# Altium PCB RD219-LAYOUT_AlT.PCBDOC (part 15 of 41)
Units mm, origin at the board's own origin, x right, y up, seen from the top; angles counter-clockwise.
Board outline 209.75 x 159.97 mm, 2 copper layers (TOP, BOTTOM), stack 0 mm thick; 398 components, 199 nets, 1469 pads, 0 vias.
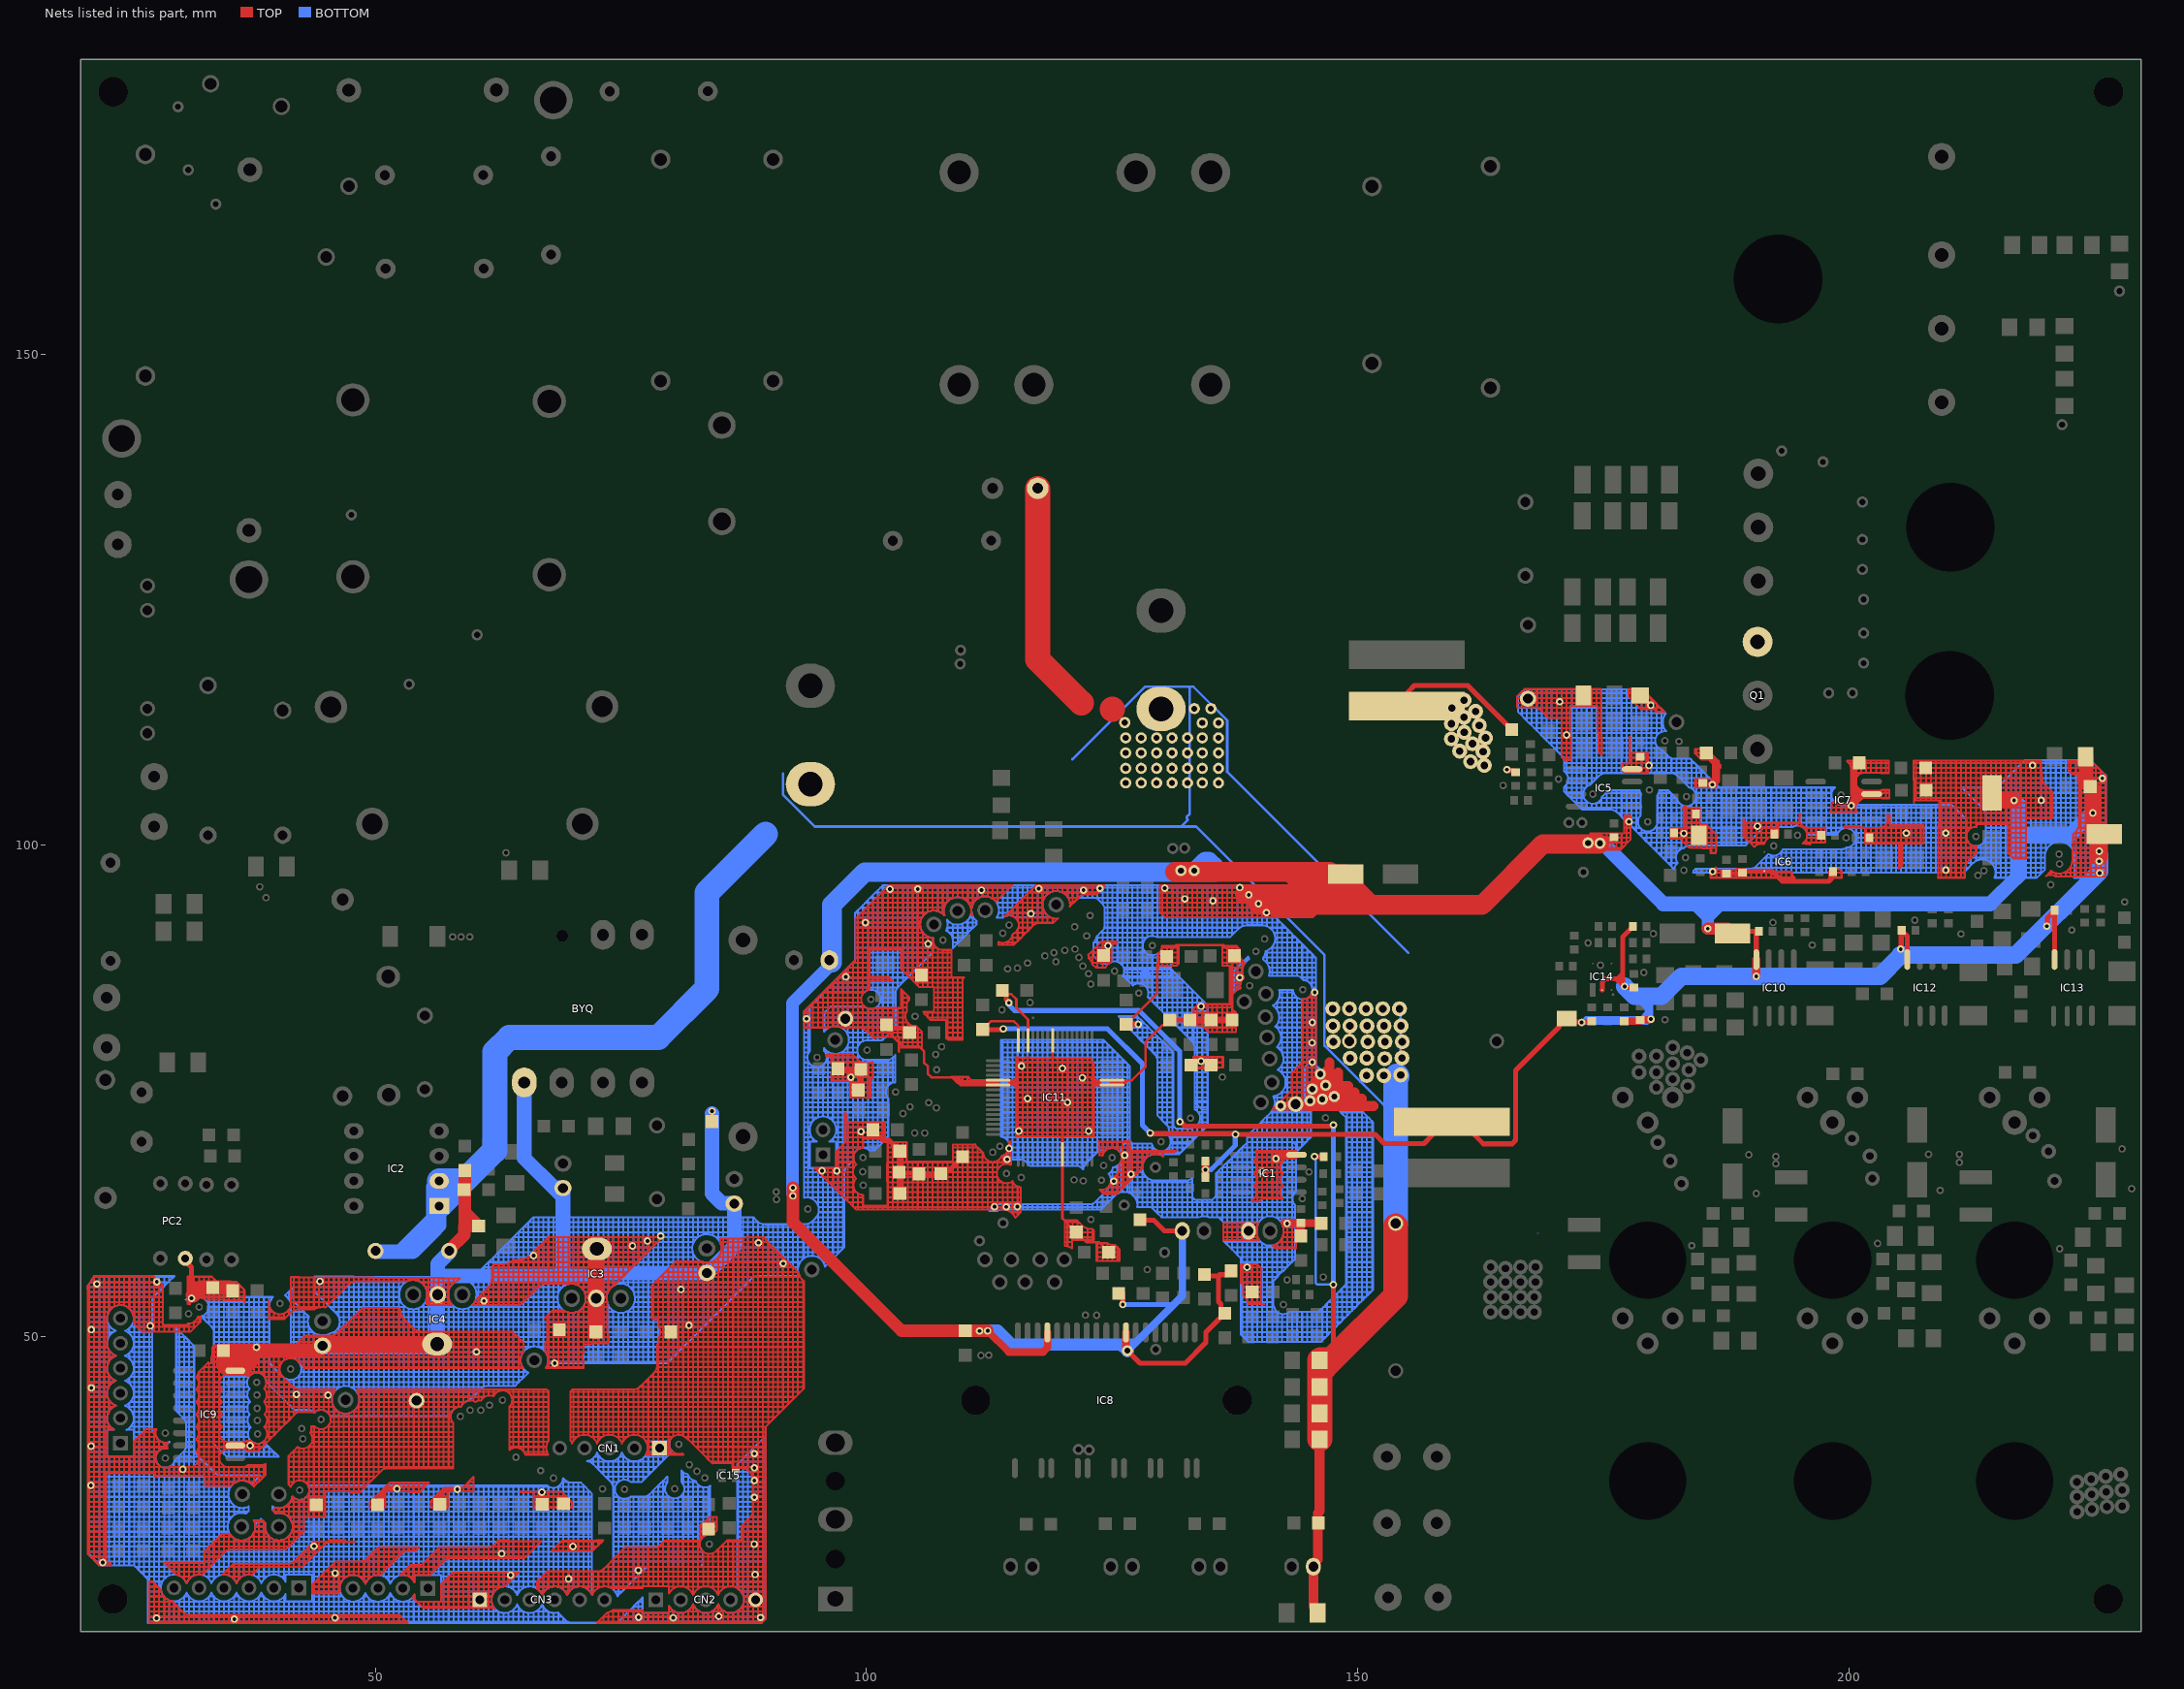
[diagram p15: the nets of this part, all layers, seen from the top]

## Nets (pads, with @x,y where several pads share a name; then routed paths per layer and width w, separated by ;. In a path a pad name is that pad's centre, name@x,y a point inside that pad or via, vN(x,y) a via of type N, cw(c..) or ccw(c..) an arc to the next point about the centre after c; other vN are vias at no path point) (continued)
GND: (continued)
  TOP w0.203: 127.569,66.736 127.569,67.244 ; 127.569,67.244 127.569,67.752 ; 127.569,67.244 128.058,67.244 ; 127.569,67.752 127.569,68.26 ; 127.569,67.752 128.077,67.752 ; 127.569,68.26 127.569,68.768 ; 127.569,68.26 128.077,68.26 ; 127.569,68.768 127.569,68.895 ; 127.569,68.768 128.077,68.768 ; 127.569,68.895 128.077,68.895 ; 127.658,66.736 128.058,67.136 128.058,67.234 cw(c129.41,67.234) 128.058,67.244 ; 128.058,67.244 cw(c129.41,67.234) 128.077,67.459 ; 128.077,67.459 cw(c129.41,67.234) 128.079,67.469 cw(c129.41,67.234) 128.161,67.752 ; 128.077,67.459 128.077,67.752 ; 128.077,67.752 128.077,68.26 ; 128.077,67.752 128.161,67.752 ; 128.077,68.26 128.077,68.768 ; 128.077,68.26 128.53,68.26 ; 128.077,68.768 128.585,68.768 ; 128.077,68.768 128.077,68.895 ; 128.077,68.895 128.585,68.895 ; 128.161,67.752 cw(c129.41,67.234) 128.53,68.26 ; 128.53,68.26 cw(c129.41,67.234) 128.585,68.305 ; 128.585,68.305 128.585,68.768 ; 128.585,68.768 128.585,68.895 ; 128.585,68.768 129.093,68.768 ; 128.585,68.895 129.093,68.895 ; 129.093,68.768 129.601,68.768 ; 129.093,68.768 129.093,68.895 ; 129.093,68.895 129.601,68.895 ; 129.601,68.572 cw(c129.41,67.234) 130.109,68.391 ; 129.601,68.572 129.601,68.768 ; 129.601,68.768 129.601,68.895 ; 129.601,68.768 130.109,68.768 ; 129.601,68.895 129.744,68.895 ccw(c129.983,69.848) 130.109,68.874 ; 129.682,87.738 130.109,87.738 ; 129.682,87.738 129.682,88.026 129.682,88.072 ; 129.682,88.072 129.728,88.072 C45.2@130.109,88.072 ; 129.682,88.072 129.682,88.58 ; 129.682,88.58 C45.2@130.109,88.58 ; 129.682,88.58 129.682,89.014 ccw(c129.091,89.799) 129.769,89.088 ; 129.769,89.088 ccw(c129.091,89.799) 129.876,89.208 ccw(c129.091,89.799) 130.052,89.596 ; 129.769,89.088 C45.2@130.109,89.088 ; 129.837,93.66 129.837,94.168 ; 129.837,93.66 129.837,93.217 129.902,93.152 ; 129.837,93.66 130.109,93.66 ; 129.837,94.168 129.837,94.676 ; 129.837,94.168 130.109,94.168 ; 129.837,94.676 129.837,95.184 ; 129.837,94.676 130.109,94.676 ; 129.837,95.184 129.837,95.692 ; 129.837,95.184 130.109,95.184 ; 129.837,95.692 129.837,95.946 130.109,95.946 ; 129.837,95.692 pad.@130.109,95.692 ; 129.902,93.152 130.109,92.945 ; 129.902,93.152 130.109,93.152 ; 130.052,89.596 ccw(c129.091,89.799) 130.073,89.756 ; 130.052,89.596 130.109,89.596 ; 130.073,89.756 130.109,89.756 ; 130.109,68.391 cw(c129.41,67.234) 130.2,68.33 ; 130.109,68.391 130.109,68.768 ; 130.109,68.768 130.617,68.768 ; 130.109,68.768 130.109,68.874 ; 130.109,68.874 ccw(c129.983,69.848) 130.22,68.895 130.617,68.895 ; 130.109,87.738 130.617,87.738 ; 130.109,87.738 C45.2@130.109,88.072 ; C45.2@130.109,88.072 130.109,88.453 C45.2@130.109,88.58 ; C45.2@130.109,88.072 C45.2@130.617,88.072 ; C45.2@130.109,88.58 130.236,88.58 C45.2@130.617,88.58 ; C45.2@130.109,88.58 C45.2@130.109,89.088 ; C45.2@130.109,89.088 130.109,89.596 ; C45.2@130.109,89.088 C45.2@130.617,89.088 ; 130.109,89.596 130.617,89.596 ; 130.109,89.596 130.109,89.756 ; 130.109,89.756 130.617,89.756 ; 130.109,92.945 130.109,93.152 ; 130.109,92.945 130.351,92.703 130.617,92.703 ; 130.109,93.152 130.109,93.66 ; 130.109,93.152 130.617,93.152 ; 130.109,93.66 130.109,94.168 ; 130.109,93.66 130.617,93.66 ; 130.109,94.168 130.109,94.676 ; 130.109,94.168 130.617,94.168 ; 130.109,94.676 130.109,95.184 ; 130.109,94.676 130.617,94.676 ; 130.109,95.184 130.617,95.184 ; 130.109,95.184 pad.@130.109,95.692 ; pad.@130.109,95.692 130.109,95.946 ; pad.@130.109,95.692 pad.@130.617,95.692 ; 130.109,95.946 130.617,95.946 ; 130.2,68.33 130.2,68.754 130.617,68.754 ; 130.617,68.754 131.125,68.754 ; 130.617,68.754 130.617,68.768 ; 130.617,68.768 131.125,68.768 ; 130.617,68.768 130.617,68.895 ; 130.617,68.895 131.125,68.895 ; 130.617,87.738 C45.2@130.617,88.072 ; 130.617,87.738 131.125,87.738 ; C45.2@130.617,88.072 C45.2@130.617,88.58 ; C45.2@130.617,88.072 C45.2@131.125,88.072 ; C45.2@130.617,88.58 C45.2@131.125,88.58 ; C45.2@130.617,88.58 130.617,88.961 C45.2@130.617,89.088 ; C45.2@130.617,89.088 130.744,89.088 C45.2@131.125,89.088 ; C45.2@130.617,89.088 130.617,89.596 ; 130.617,89.596 130.617,89.756 ; 130.617,89.596 131.125,89.596 ; 130.617,89.756 131.125,89.756 ; 130.617,92.703 130.617,93.152 ; 130.617,92.703 131.125,92.703 ; 130.617,93.152 130.617,93.66 ; 130.617,93.152 131.125,93.152 ; 130.617,93.66 130.617,94.168 ; 130.617,93.66 131.125,93.66 ; 130.617,94.168 130.617,94.676 ; 130.617,94.168 131.125,94.168 ; 130.617,94.676 130.617,95.184 ; 130.617,94.676 131.125,94.676 ; 130.617,95.184 131.125,95.184 ; 130.617,95.184 pad.@130.617,95.692 ; pad.@130.617,95.692 130.617,95.946 ; pad.@130.617,95.692 131.125,95.692 ; 130.617,95.946 131.125,95.946 ; 131.125,68.754 131.125,68.768 ; 131.125,68.754 131.281,68.754 ; 131.125,68.768 131.125,68.895 ; 131.125,68.768 131.3,68.768 ; 131.125,87.738 C45.2@131.125,88.072 ; 131.125,87.738 131.555,87.738 131.633,87.815 ; C45.2@131.125,88.072 131.633,88.072 ; C45.2@131.125,88.072 C45.2@131.125,88.58 ; C45.2@131.125,88.58 131.633,88.58 ; C45.2@131.125,88.58 C45.2@131.125,89.088 ; C45.2@131.125,89.088 131.633,89.088 ; C45.2@131.125,89.088 131.125,89.469 131.125,89.596 ; 131.125,89.596 131.252,89.596 131.633,89.596 ; 131.125,89.596 131.125,89.756 ; 131.125,89.756 131.412,89.756 131.633,89.756 ; 131.125,92.703 131.125,93.152 ; 131.125,92.703 131.633,92.703 ; 131.125,93.152 131.125,93.66 ; 131.125,93.152 131.633,93.152 ; 131.125,93.66 131.125,94.168 ; 131.125,93.66 131.633,93.66 ; 131.125,94.168 131.125,94.676 ; 131.125,94.168 131.633,94.168 ; 131.125,94.676 131.125,95.184 ; 131.125,94.676 131.633,94.676 ; 131.125,95.184 131.125,95.692 ; 131.125,95.184 131.633,95.184 ; 131.125,95.692 131.125,95.946 ; 131.125,95.692 131.633,95.692 ; 131.125,95.946 131.633,95.946 ; 131.281,68.754 cw(c131.729,68.179) 131.3,68.768 ; 131.281,68.754 cw(c131.729,68.179) 131.3,68.768 ; 131.3,68.768 cw(c131.729,68.179) 131.59,68.894 ccw(c131.729,68.179) 131.3,68.768 ; 131.633,87.815 131.633,88.072 ; 131.633,87.815 131.778,87.961 131.778,88.072 ; 131.633,88.072 131.633,88.58 ; 131.633,88.072 131.778,88.072 ; 131.633,88.58 131.633,89.088 ; 131.633,88.58 131.778,88.58 ; 131.633,89.088 131.778,89.088 ; 131.633,89.088 131.633,89.596 ; 131.633,89.596 131.778,89.596 ; 131.633,89.596 131.633,89.756 ; 131.633,89.756 131.778,89.756 131.778,89.596 ; 131.633,92.703 131.633,93.152 ; 131.633,92.703 132.141,92.703 ; 131.633,93.152 131.633,93.66 ; 131.633,93.152 132.141,93.152 ; 131.633,93.66 131.633,94.168 ; 131.633,93.66 132.141,93.66 ; 131.633,94.168 131.633,94.676 ; 131.633,94.168 132.141,94.168 ; 131.633,94.676 131.633,95.184 ; 131.633,94.676 pad.@132.141,94.676 ; 131.633,95.184 131.633,95.692 ; 131.633,95.184 132.141,95.184 ; 131.633,95.692 131.633,95.946 ; 131.633,95.692 132.141,95.692 ; 131.633,95.946 132.141,95.946 ; 131.778,88.072 131.778,88.58 ; 131.778,88.58 131.778,89.088 ; 131.778,89.088 131.778,89.596 ; 132.141,92.703 132.141,93.152 ; 132.141,92.703 132.649,92.703 ; 132.141,93.152 132.141,93.66 ; 132.141,93.152 132.649,93.152 ; 132.141,93.66 132.141,94.168 ; 132.141,93.66 132.649,93.66 ; 132.141,94.168 132.649,94.168 ; 132.141,94.168 pad.@132.141,94.676 ; pad.@132.141,94.676 132.141,95.184 ; pad.@132.141,94.676 pad.@132.649,94.676 ; 132.141,95.184 132.141,95.692 ; 132.141,95.184 132.649,95.184 ; 132.141,95.692 132.141,95.946 ; 132.141,95.692 132.649,95.692 ; 132.141,95.946 132.649,95.946 ; 132.649,92.703 132.649,93.152 ; 132.649,92.703 133.157,92.703 ; 132.649,93.152 132.649,93.66 ; 132.649,93.152 133.157,93.152 ; 132.649,93.66 132.649,94.168 ; 132.649,93.66 133.157,93.66 ; 132.649,94.168 133.157,94.168 ; 132.649,94.168 pad.@132.649,94.676 ; pad.@132.649,94.676 132.649,95.184 ; pad.@132.649,94.676 133.157,94.676 ; 132.649,95.184 132.649,95.692 ; 132.649,95.184 133.157,95.184 ; 132.649,95.692 132.649,95.946 ; 132.649,95.692 133.157,95.692 ; 132.649,95.946 133.157,95.946 ; 133.157,92.703 133.157,93.152 ; 133.157,92.703 133.665,92.703 ; 133.157,93.152 133.157,93.66 ; 133.157,93.152 133.665,93.152 ; 133.157,93.66 133.157,94.168 ; 133.157,93.66 133.665,93.66 ; 133.157,94.168 133.157,94.676 ; 133.157,94.168 133.665,94.168 ; 133.157,94.676 133.157,95.184 ; 133.157,94.676 133.665,94.676 ; 133.157,95.184 133.157,95.692 ; 133.157,95.184 133.665,95.184 ; 133.157,95.692 133.157,95.946 ; 133.157,95.692 133.665,95.692 ; 133.157,95.946 133.665,95.946 ; C65.2@133.284,77.404 C65.2@133.665,77.404 ; C65.2@133.284,77.404 133.284,77.283 C65.2@133.665,77.283 ; C65.2@133.284,77.404 C65.2@133.284,77.912 ; C65.2@133.284,77.912 C65.2@133.665,77.912 ; C65.2@133.284,77.912 133.284,78.42 ; 133.284,78.42 133.665,78.42 ; 133.284,78.42 133.284,78.489 133.665,78.489 ; C43.1@133.284,81.976 133.665,81.976 ; C43.1@133.284,81.976 133.284,81.689 133.665,81.689 ; C43.1@133.284,81.976 133.284,82.23 C43.1@133.284,82.484 ; C43.1@133.284,82.484 133.665,82.484 ; C43.1@133.284,82.484 133.284,82.992 ; 133.284,82.992 133.665,82.992 ; 133.284,82.992 133.284,83.359 133.425,83.5 ; 133.425,83.5 133.665,83.5 ; 133.425,83.5 133.665,83.74 ; C65.2@133.665,77.283 134.173,77.283 ; C65.2@133.665,77.283 C65.2@133.665,77.404 ; C65.2@133.665,77.404 134.173,77.404 ; C65.2@133.665,77.404 C65.2@133.665,77.912 ; C65.2@133.665,77.912 pad.@134.173,77.912 ; C65.2@133.665,77.912 133.665,78.42 ; 133.665,78.42 133.665,78.489 ; 133.665,78.42 134.173,78.42 ; 133.665,78.489 134.173,78.489 ; 133.665,81.689 133.665,81.976 ; 133.665,81.689 133.843,81.689 ; 133.665,81.976 134.173,81.976 ; 133.665,81.976 133.665,82.23 133.665,82.484 ; 133.665,82.484 134.173,82.484 ; 133.665,82.484 133.665,82.992 ; 133.665,82.992 134.173,82.992 ; 133.665,82.992 133.665,83.5 ; 133.665,83.5 pad.@134.173,83.5 ; 133.665,83.5 133.665,83.74 ; 133.665,83.74 133.76,83.834 pad.@134.173,83.834 ; 133.665,92.703 133.665,93.152 ; 133.665,92.703 134.173,92.703 ; 133.665,93.152 133.665,93.66 ; 133.665,93.152 134.173,93.152 ; 133.665,93.66 133.665,94.168 ; 133.665,93.66 134.173,93.66 ; 133.665,94.168 133.665,94.676 ; 133.665,94.168 134.173,94.168 ; 133.665,94.676 133.665,95.184 ; 133.665,94.676 134.173,94.676 ; 133.665,95.184 133.665,95.692 ; 133.665,95.184 134.173,95.184 ; 133.665,95.692 133.665,95.946 ; 133.665,95.692 134.173,95.692 ; 133.665,95.946 134.173,95.946 ; 133.843,81.689 cw(c133.843,80.96) 134.173,81.609 ; 133.843,81.689 cw(c133.843,80.96) 134.173,81.609 ; 134.173,77.283 C56.2@134.681,77.283 ; 134.173,77.283 134.173,77.404 ; 134.173,77.404 C56.2@134.681,77.404 ; 134.173,77.404 pad.@134.173,77.912 ; pad.@134.173,77.912 C56.2@134.681,77.912 ; pad.@134.173,77.912 134.173,78.42 ; 134.173,78.42 134.681,78.42 ; 134.173,78.42 134.173,78.489 ; 134.173,78.489 134.681,78.489 ; 134.173,81.609 cw(c133.843,80.96) 134.358,81.475 ; 134.173,81.609 cw(c133.843,80.96) 134.358,81.475 ; 134.173,81.609 134.173,81.976 ; 134.173,81.976 C40.1@134.681,81.976 ; 134.173,81.976 134.173,82.23 134.173,82.484 ; 134.173,82.484 C40.1@134.681,82.484 ; 134.173,82.484 134.173,82.992 ; 134.173,82.992 134.681,82.992 ; 134.173,82.992 pad.@134.173,83.5 ; pad.@134.173,83.5 134.681,83.5 ; pad.@134.173,83.5 pad.@134.173,83.834 ; pad.@134.173,83.834 134.681,83.834 ; 134.173,92.703 134.173,93.152 ; 134.173,92.703 134.681,92.703 ; 134.173,93.152 134.173,93.66 ; 134.173,93.152 134.681,93.152 ; 134.173,93.66 134.173,94.168 ; 134.173,93.66 134.681,93.66 ; 134.173,94.168 134.173,94.676 ; 134.173,94.168 134.681,94.168 ; 134.173,94.676 134.173,95.184 ; 134.173,94.676 134.681,94.676 ; 134.173,95.184 134.173,95.692 ; 134.173,95.184 134.681,95.184 ; 134.173,95.692 134.173,95.946 ; 134.173,95.692 134.681,95.692 ; 134.173,95.946 134.681,95.946 ; 134.358,81.475 134.681,81.152 ; C56.2@134.681,77.283 C56.2@134.681,77.404 ; C56.2@134.681,77.283 C56.2@135.189,77.283 ; C56.2@134.681,77.404 C56.2@135.189,77.404 ; C56.2@134.681,77.404 C56.2@134.681,77.912 ; C56.2@134.681,77.912 134.681,78.42 ; C56.2@134.681,77.912 C56.2@135.189,77.912 ; 134.681,78.42 135.189,78.42 ; 134.681,78.42 134.681,78.489 ; 134.681,78.489 135.189,78.489 ; 134.681,81.152 134.841,80.992 135.189,80.992 ; 134.681,81.152 134.681,81.468 ; 134.681,81.468 135.189,81.468 ; 134.681,81.468 C40.1@134.681,81.976 ; C40.1@134.681,81.976 134.681,82.23 C40.1@134.681,82.484 ; C40.1@134.681,81.976 C40.1@135.189,81.976 ; C40.1@134.681,82.484 134.681,82.992 ; C40.1@134.681,82.484 C40.1@135.189,82.484 ; 134.681,82.992 135.189,82.992 ; 134.681,82.992 134.681,83.5 ; 134.681,83.5 135.189,83.5 ; 134.681,83.5 134.681,83.834 ; 134.681,83.834 135.189,83.834 ; 134.681,92.703 134.681,93.152 ; 134.681,92.703 135.189,92.703 ; 134.681,93.152 134.681,93.66 ; 134.681,93.152 135.189,93.152 ; 134.681,93.66 134.681,94.168 ; 134.681,93.66 135.189,93.66 ; 134.681,94.168 134.681,94.676 ; 134.681,94.168 pad.@135.189,94.168 ; 134.681,94.676 134.681,95.184 ; 134.681,94.676 pad.@135.189,94.676 ; 134.681,95.184 134.681,95.692 ; 134.681,95.184 135.189,95.184 ; 134.681,95.692 134.681,95.946 ; 134.681,95.692 135.189,95.692 ; 134.681,95.946 135.189,95.946 ; C56.2@135.189,77.283 C56.2@135.697,77.283 ; C56.2@135.189,77.283 C56.2@135.189,77.404 ; C56.2@135.189,77.404 C56.2@135.697,77.404 ; C56.2@135.189,77.404 C56.2@135.189,77.912 ; C56.2@135.189,77.912 C56.2@135.697,77.912 ; C56.2@135.189,77.912 135.189,78.42 ; 135.189,78.42 135.697,78.42 ; 135.189,78.42 135.189,78.489 ; 135.189,78.489 135.697,78.489 ; 135.189,80.992 135.189,81.468 ; 135.189,80.992 135.697,80.992 ; 135.189,81.468 C40.1@135.189,81.976 ; 135.189,81.468 135.697,81.468 ; C40.1@135.189,81.976 C40.1@135.697,81.976 ; C40.1@135.189,81.976 135.189,82.23 C40.1@135.189,82.484 ; C40.1@135.189,82.484 135.189,82.992 ; C40.1@135.189,82.484 C40.1@135.697,82.484 ; 135.189,82.992 135.189,83.5 ; 135.189,82.992 135.697,82.992 ; 135.189,83.5 135.189,83.834 ; 135.189,83.5 135.697,83.5 ; 135.189,83.834 135.697,83.834 ; 135.189,92.703 135.189,93.152 ; 135.189,92.703 135.697,92.703 ; 135.189,93.152 135.189,93.66 ; 135.189,93.152 135.697,93.152 ; 135.189,93.66 pad.@135.189,94.168 ; 135.189,93.66 135.697,93.66 ; pad.@135.189,94.168 pad.@135.189,94.676 ; pad.@135.189,94.168 135.697,94.168 ; pad.@135.189,94.676 135.189,95.184 ; pad.@135.189,94.676 135.697,94.676 ; 135.189,95.184 135.189,95.692 ; 135.189,95.184 135.697,95.184 ; 135.189,95.692 135.189,95.946 ; 135.189,95.692 135.697,95.692 ; 135.189,95.946 135.697,95.946 ; C56.2@135.697,77.283 C56.2@135.697,77.404 ; C56.2@135.697,77.404 136.109,77.404 ; C56.2@135.697,77.404 C56.2@135.697,77.912 ; C56.2@135.697,77.912 136.205,77.912 ; C56.2@135.697,77.912 135.697,78.42 ; 135.697,78.42 136.205,78.42 ; 135.697,78.42 135.697,78.489 ; 135.697,78.489 136.205,78.489 ; 135.697,80.992 135.697,81.468 ; 135.697,80.992 136.205,80.992 ; 135.697,81.468 136.205,81.468 ; 135.697,81.468 C40.1@135.697,81.976 ; C40.1@135.697,81.976 136.205,81.976 ; C40.1@135.697,81.976 135.697,82.23 C40.1@135.697,82.484 ; C40.1@135.697,82.484 136.205,82.484 ; C40.1@135.697,82.484 135.697,82.992 ; 135.697,82.992 136.205,82.992 ; 135.697,82.992 135.697,83.5 ; 135.697,83.5 136.205,83.5 ; 135.697,83.5 135.697,83.834 ; 135.697,83.834 136.205,83.834 ; 135.697,92.703 135.697,93.152 ; 135.697,92.703 136.205,92.703 ; 135.697,93.152 135.697,93.66 ; 135.697,93.152 136.205,93.152 ; 135.697,93.66 135.697,94.168 ; 135.697,93.66 136.205,93.66 ; 135.697,94.168 136.205,94.168 ; 135.697,94.168 135.697,94.676 ; 135.697,94.676 135.697,95.184 ; 135.697,94.676 136.205,94.676 ; 135.697,95.184 135.697,95.692 ; 135.697,95.184 136.205,95.184 ; 135.697,95.692 135.697,95.946 ; 135.697,95.692 136.205,95.692 ; 135.697,95.946 136.205,95.946 ; 136.109,77.404 cw(c136.214,76.427) 136.205,77.41 ; 136.205,77.41 cw(c136.214,76.427) 136.3,77.406 136.3,77.912 ; 136.205,77.41 136.205,77.912 ; 136.205,77.912 136.3,77.912 ; 136.205,77.912 136.205,78.42 ; 136.205,78.42 136.3,78.42 ; 136.205,78.42 136.205,78.489 ; 136.205,78.489 136.3,78.489 136.3,78.42 ; 136.205,80.992 136.205,81.468 ; 136.205,80.992 136.713,80.992 ; 136.205,81.468 136.205,81.976 ; 136.205,81.468 136.713,81.468 ; 136.205,81.976 136.205,82.23 136.205,82.484 ; 136.205,81.976 C41.1@136.713,81.976 ; 136.205,82.484 136.205,82.992 ; 136.205,82.484 C41.1@136.713,82.484 ; 136.205,82.992 136.205,83.5 ; 136.205,82.992 136.713,82.992 ; 136.205,83.5 136.713,83.5 ; 136.205,83.5 136.205,83.834 ; 136.205,83.834 136.713,83.834 ; 136.205,92.703 136.205,93.152 ; 136.205,92.703 136.713,92.703 ; 136.205,93.152 136.205,93.66 ; 136.205,93.152 136.713,93.152 ; 136.205,93.66 136.205,94.168 ; 136.205,93.66 136.713,93.66 ; 136.205,94.168 136.205,94.676 ; 136.205,94.168 136.713,94.168 ; 136.205,94.676 136.205,95.184 ; 136.205,94.676 136.713,94.676 ; 136.205,95.184 136.205,95.692 ; 136.205,95.184 136.713,95.184 ; 136.205,95.692 136.205,95.946 ; 136.205,95.692 136.713,95.692 ; 136.205,95.946 136.713,95.946 ; 136.212,88.072 136.212,88.58 ; 136.212,88.072 136.212,87.738 136.713,87.738 ; 136.212,88.072 136.713,88.072 ; 136.212,88.58 136.212,89.088 ; 136.212,88.58 136.713,88.58 ; 136.212,89.088 136.212,89.596 ; 136.212,89.088 136.713,89.088 ; 136.212,89.596 136.612,89.596 136.713,89.596 ; 136.212,89.596 136.212,89.756 136.452,89.756 136.713,89.756 ; 136.3,77.912 136.3,78.42 ; 136.332,60.132 136.332,60.64 ; 136.332,60.132 136.713,60.132 ; 136.332,60.132 136.332,59.825 136.713,59.825 ; 136.332,60.64 136.332,61.148 ; 136.332,60.64 136.713,60.64 ; 136.332,61.148 136.332,61.562 136.713,61.562 ; 136.332,61.148 136.713,61.148 ; 136.713,59.825 137.221,59.825 ; 136.713,59.825 136.713,60.132 ; 136.713,60.132 136.713,60.64 ; 136.713,60.132 137.221,60.132 ; 136.713,60.64 137.221,60.64 ; 136.713,60.64 136.713,61.148 ; 136.713,61.148 137.221,61.148 ; 136.713,61.148 136.713,61.562 ; 136.713,61.562 137.221,61.562 ; 136.713,80.992 137.221,80.992 ; 136.713,80.992 136.713,81.468 ; 136.713,81.468 137.221,81.468 ; 136.713,81.468 C41.1@136.713,81.976 ; C41.1@136.713,81.976 C41.1@137.221,81.976 ; C41.1@136.713,81.976 136.713,82.23 C41.1@136.713,82.484 ; C41.1@136.713,82.484 C41.1@137.221,82.484 ; C41.1@136.713,82.484 136.713,82.992 ; 136.713,82.992 137.221,82.992 ; 136.713,82.992 136.713,83.5 ; 136.713,83.5 136.713,83.834 ; 136.713,83.5 137.182,83.5 ; 136.713,83.834 136.986,83.834 136.986,84.516 ; 136.713,87.738 136.713,88.072 ; 136.713,87.738 136.986,87.738 136.986,87.564 ; 136.713,88.072 136.713,88.58 ; 136.713,88.072 137.221,88.072 ; 136.713,88.58 C44.2@137.221,88.58 ; 136.713,88.58 136.713,89.088 ; 136.713,89.088 137.12,89.088 C44.2@137.221,89.088 ; 136.713,89.088 136.713,89.495 136.713,89.596 ; 136.713,89.596 136.713,89.756 ; 136.713,89.596 137.221,89.596 ; 136.713,89.756 137.221,89.756 ; 136.713,92.703 136.713,93.152 ; 136.713,92.703 137.221,92.703 ; 136.713,93.152 136.713,93.66 ; 136.713,93.152 137.221,93.152 ; 136.713,93.66 136.713,94.168 ; 136.713,93.66 137.221,93.66 ; 136.713,94.168 136.713,94.676 ; 136.713,94.168 137.221,94.168 ; 136.713,94.676 136.713,95.184 ; 136.713,94.676 137.221,94.676 ; 136.713,95.184 136.713,95.692 ; 136.713,95.184 137.221,95.184 ; 136.713,95.692 136.713,95.946 ; 136.713,95.692 137.221,95.692 ; 136.713,95.946 137.221,95.946 ; 136.986,84.516 136.986,85.024 ; 136.986,85.024 136.986,85.532 ; 136.986,85.024 137.221,85.024 ; 136.986,85.532 136.986,86.04 ; 136.986,85.532 137.221,85.532 ; 136.986,86.04 136.986,86.548 ; 136.986,86.04 137.221,86.04 ; 136.986,86.548 136.986,87.056 ; 136.986,86.548 137.221,86.548 ; 136.986,87.056 136.986,87.564 ; 136.986,87.056 137.221,87.056 ; 136.986,87.564 137.221,87.564 ; 137.182,83.5 ccw(c138.451,84.095) 137.221,83.423 ; 137.221,59.825 137.729,59.825 ; 137.221,59.825 137.221,60.132 ; 137.221,60.132 137.221,60.64 ; 137.221,60.132 137.729,60.132 ; 137.221,60.64 137.221,61.148 ; 137.221,60.64 137.729,60.64 ; 137.221,61.148 137.221,61.562 ; 137.221,61.148 137.729,61.148 ; 137.221,61.562 137.729,61.562 ; 137.221,80.992 137.221,81.468 ; 137.221,80.992 137.584,80.992 137.584,81.468 ; 137.221,81.468 C41.1@137.221,81.976 ; 137.221,81.468 137.584,81.468 ; C41.1@137.221,81.976 C41.1@137.221,82.23 C41.1@137.221,82.484 ; C41.1@137.221,81.976 C41.1@137.584,81.976 ; C41.1@137.221,82.484 137.221,82.992 ; C41.1@137.221,82.484 C41.1@137.584,82.484 ; 137.221,82.992 137.584,82.992 ; 137.221,82.992 137.221,83.423 ; 137.221,83.423 ccw(c138.451,84.095) 137.584,82.993 ; 137.221,84.767 cw(c138.451,84.095) 137.225,84.775 cw(c138.451,84.095) 137.402,85.024 ; 137.221,84.767 137.221,85.024 ; 137.221,85.024 137.221,85.532 ; 137.221,85.024 137.402,85.024 ; 137.221,85.532 137.729,85.532 ; 137.221,85.532 137.221,86.04 ; 137.221,86.04 137.221,86.548 ; 137.221,86.04 137.729,86.04 ; 137.221,86.548 pad.@137.729,86.548 ; 137.221,86.548 137.221,87.056 ; 137.221,87.056 137.729,87.056 ; 137.221,87.056 137.221,87.564 ; 137.221,87.564 137.729,87.564 ; 137.221,87.564 137.221,88.072 ; 137.221,88.072 C44.2@137.221,88.58 ; 137.221,88.072 137.729,88.072 ; C44.2@137.221,88.58 137.271,88.58 137.551,88.58 C44.2@137.729,88.58 ; C44.2@137.221,88.58 137.221,88.987 C44.2@137.221,89.088 ; C44.2@137.221,89.088 137.221,89.596 ; C44.2@137.221,89.088 C44.2@137.729,89.088 ; 137.221,89.596 137.729,89.596 ; 137.221,89.596 137.221,89.756 ; 137.221,89.756 137.681,89.756 137.729,89.709 ; 137.221,92.703 137.729,92.703 ; 137.221,92.703 137.221,93.152 ; 137.221,93.152 137.729,93.152 ; 137.221,93.152 137.221,93.66 ; 137.221,93.66 137.729,93.66 ; 137.221,93.66 137.221,94.168 ; 137.221,94.168 137.729,94.168 ; 137.221,94.168 137.221,94.676 ; 137.221,94.676 137.729,94.676 ; 137.221,94.676 137.221,95.184 ; 137.221,95.184 137.729,95.184 ; 137.221,95.184 137.221,95.692 ; 137.221,95.692 pad.@137.729,95.692 ; 137.221,95.692 137.221,95.946 ; 137.221,95.946 pad.@137.729,95.946 ; 137.402,85.024 cw(c138.451,84.095) 137.729,85.296 ; 137.584,81.468 C41.1@137.584,81.976 ; C41.1@137.584,81.976 C41.1@137.584,82.484 ; C41.1@137.584,82.484 137.584,82.992 ; 137.584,82.992 137.584,82.993 ; 137.729,59.825 138.237,59.825 ; 137.729,59.825 137.729,60.132 ; 137.729,60.132 137.729,60.64 ; 137.729,60.132 138.237,60.132 ; 137.729,60.64 EC16.2@138.237,60.64 ; 137.729,60.64 137.729,61.148 ; 137.729,61.148 EC16.2@138.237,61.148 ; 137.729,61.148 137.729,61.562 ; 137.729,61.562 138.237,61.562 ; 137.729,85.296 137.729,85.532 ; 137.729,85.532 137.729,86.04 ; 137.729,85.532 138.013,85.532 ; 137.729,86.04 138.071,86.04 ; 137.729,86.04 pad.@137.729,86.548 ; pad.@137.729,86.548 pad.@137.983,86.548 pad.@138.237,86.548 ; pad.@137.729,86.548 137.729,87.056 ; 137.729,87.056 137.729,87.564 ; 137.729,87.056 138.237,87.056 ; 137.729,87.564 137.729,88.072 ; 137.729,87.564 138.237,87.564 ; 137.729,88.072 C44.2@137.729,88.58 ; 137.729,88.072 138.237,88.072 ; C44.2@137.729,88.58 C44.2@137.729,89.088 ; C44.2@137.729,88.58 C44.2@138.062,88.58 ; C44.2@137.729,89.088 137.729,89.596 ; C44.2@137.729,89.088 C44.2@138.016,89.088 ; 137.729,89.596 137.729,89.709 ; 137.729,89.596 137.842,89.596 ; 137.729,89.709 137.842,89.596 ; 137.729,92.703 138.237,92.703 ; 137.729,92.703 137.729,93.152 ; 137.729,93.152 138.237,93.152 ; 137.729,93.152 137.729,93.66 ; 137.729,93.66 138.237,93.66 ; 137.729,93.66 137.729,94.168 ; 137.729,94.168 138.237,94.168 ; 137.729,94.168 137.729,94.676 ; 137.729,94.676 138.237,94.676 ; 137.729,94.676 137.729,95.184 ; 137.729,95.184 138.237,95.184 ; 137.729,95.184 pad.@137.729,95.692 ; pad.@137.729,95.692 pad.@138.237,95.692 ; pad.@137.729,95.692 pad.@137.729,95.946 ; pad.@137.729,95.946 pad.@138.237,95.946 ; 137.842,89.596 138.016,89.421 C44.2@138.016,89.088 ; 138.013,85.532 ccw(c138.695,85.276) 137.98,85.415 cw(c138.695,85.276) 138.013,85.532 ; 138.013,85.532 cw(c138.695,85.276) 138.028,85.568 ; 138.013,85.532 cw(c138.695,85.276) 138.028,85.568 ; C44.2@138.016,88.834 ccw(c138.745,88.834) C44.2@138.062,88.58 ; C44.2@138.016,88.834 ccw(c138.745,88.834) C44.2@138.062,88.58 ; C44.2@138.016,88.834 C44.2@138.016,89.088 ; 138.028,85.568 cw(c138.999,85.717) 138.07,86.037 cw(c138.999,85.717) 138.071,86.04 ; 138.028,85.568 cw(c138.695,85.276) 138.03,85.572 ccw(c138.695,85.276) 138.028,85.568 ; C44.2@138.062,88.58 ccw(c138.745,88.834) 138.23,88.319 ; C44.2@138.062,88.58 ccw(c138.745,88.834) 138.23,88.319 ; 138.071,86.04 cw(c138.999,85.717) pad.@138.237,86.338 ; 138.11,55.56 138.237,55.56 ; 138.11,55.56 138.11,56.068 ; 138.11,55.56 138.11,55.465 138.237,55.465 ; 138.11,56.068 138.11,56.576 ; 138.11,56.068 138.237,56.068 ; 138.11,56.576 138.237,56.576 ; 138.11,56.576 138.11,57.084 ; 138.11,57.084 138.237,57.084 ; 138.11,57.084 138.11,57.352 138.237,57.352 ; 138.23,88.319 138.237,88.312 ; 138.237,55.465 138.346,55.465 138.346,55.052 ; 138.237,55.465 138.237,55.56 ; 138.237,55.56 138.745,55.56 ; 138.237,55.56 138.237,56.068 ; 138.237,56.068 138.237,56.576 ; 138.237,56.068 138.745,56.068 ; 138.237,56.576 138.237,57.084 ; 138.237,56.576 138.745,56.576 ; 138.237,57.084 138.237,57.352 ; 138.237,57.084 pad.@138.745,57.084 ; 138.237,57.352 pad.@138.745,57.352 ; 138.237,59.825 138.745,59.825 ; 138.237,59.825 138.237,60.132 ; 138.237,60.132 EC16.2@138.237,60.64 ; 138.237,60.132 EC16.2@138.745,60.132 ; EC16.2@138.237,60.64 EC16.2@138.745,60.64 ; EC16.2@138.237,60.64 EC16.2@138.237,61.148 ; EC16.2@138.237,61.148 EC16.2@138.745,61.148 ; EC16.2@138.237,61.148 138.237,61.562 ; 138.237,61.562 EC16.2@138.745,61.562 ; pad.@138.237,86.338 pad.@138.237,86.548 ; pad.@138.237,86.548 138.385,86.548 ; pad.@138.237,86.548 138.237,87.056 ; 138.237,87.056 138.237,87.07 ; 138.237,87.07 ccw(c139.634,87.183) 138.238,87.056 ccw(c139.634,87.183) 138.385,86.548 ; 138.237,87.07 cw(c139.634,87.183) 138.237,87.296 ; 138.237,87.296 cw(c139.634,87.183) 138.285,87.564 ; 138.237,87.296 138.237,87.564 ; 138.237,87.564 138.237,88.072 ; 138.237,87.564 138.285,87.564 ; 138.237,88.072 138.237,88.312 ; 138.237,88.072 138.477,88.072 ; 138.237,88.312 138.477,88.072 ; 138.237,92.703 138.745,92.703 ; 138.237,92.703 138.237,93.152 ; 138.237,93.152 138.745,93.152 ; 138.237,93.152 138.237,93.66 ; 138.237,93.66 138.745,93.66 ; 138.237,93.66 138.237,94.168 ; 138.237,94.168 138.745,94.168 ; 138.237,94.168 138.237,94.676 ; 138.237,94.676 pad.@138.745,94.676 ; 138.237,94.676 138.237,95.184 ; 138.237,95.184 pad.@138.745,95.184 ; 138.237,95.184 pad.@138.237,95.692 ; pad.@138.237,95.692 138.618,95.692 ; pad.@138.237,95.692 pad.@138.237,95.946 ; pad.@138.237,95.946 138.364,95.946 138.618,95.692 ; 138.346,54.544 R56.2@138.745,54.544 ; 138.346,54.544 138.346,55.052 ; 138.346,54.544 138.346,54.172 138.482,54.036 ; 138.346,55.052 R56.2@138.745,55.052 ; 138.482,54.036 R56.2@138.745,54.036 ; 138.482,54.036 138.588,53.93 ; 138.588,53.93 cw(c137.983,53.325) 138.745,53.714 ; 138.588,53.93 cw(c137.983,53.325) 138.745,53.714 ; 138.618,95.692 138.745,95.565 ; 138.745,53.714 cw(c137.983,53.325) 138.813,53.532 ; 138.745,53.714 cw(c137.983,53.325) 138.813,53.532 ; 138.745,53.714 R56.2@138.745,54.036 ; R56.2@138.745,54.036 R56.2@139.253,54.036 ; R56.2@138.745,54.036 R56.2@138.745,54.544 ; R56.2@138.745,54.544 R56.2@139.253,54.544 ; R56.2@138.745,54.544 R56.2@138.745,55.052 ; R56.2@138.745,55.052 138.745,55.56 ; R56.2@138.745,55.052 R56.2@139.253,55.052 ; 138.745,55.56 138.745,56.068 ; 138.745,55.56 139.253,55.56 ; 138.745,56.068 138.745,56.576 ; 138.745,56.068 139.253,56.068 ; 138.745,56.576 139.253,56.576 ; 138.745,56.576 pad.@138.745,57.084 ; pad.@138.745,57.084 pad.@138.745,57.352 ; pad.@138.745,57.084 139.253,57.084 ; pad.@138.745,57.352 139.253,57.352 ; 138.745,59.825 EC16.2@138.745,60.132 ; 138.745,59.825 139.253,59.825 ; EC16.2@138.745,60.132 EC16.2@138.745,60.64 ; EC16.2@138.745,60.132 EC16.2@139.253,60.132 ; EC16.2@138.745,60.64 EC16.2@138.745,61.148 ; EC16.2@138.745,60.64 EC16.2@139.253,60.64 ; EC16.2@138.745,61.148 EC16.2@138.745,61.562 ; EC16.2@138.745,61.148 EC16.2@139.253,61.148 ; EC16.2@138.745,61.562 EC16.2@139.253,61.562 ; 138.745,92.703 139.253,92.703 ; 138.745,92.703 138.745,93.152 ; 138.745,93.152 139.253,93.152 ; 138.745,93.152 138.745,93.66 ; 138.745,93.66 139.253,93.66 ; 138.745,93.66 138.745,94.168 ; 138.745,94.168 139.253,94.168 ; 138.745,94.168 pad.@138.745,94.676 ; pad.@138.745,94.676 139.253,94.676 ; pad.@138.745,94.676 138.745,95.056 pad.@138.745,95.184 ; pad.@138.745,95.184 138.745,95.565 ; pad.@138.745,95.184 pad.@139.126,95.184 ; 138.745,95.565 pad.@139.126,95.184 ; 138.814,53.528 ccw(c137.983,53.325) 138.813,53.532 ; 138.814,53.528 ccw(c137.983,53.325) 138.813,53.532 ; 138.814,53.528 cw(c137.983,53.325) 138.839,53.325 ccw(c137.983,53.325) 138.814,53.528 ; 138.814,53.528 139.253,53.528 ; pad.@139.126,95.184 pad.@139.253,95.057 ; 139.253,53.306 139.761,53.306 ; 139.253,53.306 139.253,53.528 ; 139.253,53.528 R56.2@139.253,54.036 ; 139.253,53.528 139.761,53.528 ; R56.2@139.253,54.036 R56.2@139.253,54.544 ; R56.2@139.253,54.036 R56.2@139.761,54.036 ; R56.2@139.253,54.544 R56.2@139.253,55.052 ; R56.2@139.253,54.544 R56.2@139.761,54.544 ; R56.2@139.253,55.052 139.253,55.56 ; R56.2@139.253,55.052 R56.2@139.761,55.052 ; 139.253,55.56 139.761,55.56 ; 139.253,55.56 139.253,56.068 ; 139.253,56.068 139.253,56.576 ; 139.253,56.068 139.761,56.068 ; 139.253,56.576 139.761,56.576 ; 139.253,56.576 139.253,57.084 ; 139.253,57.084 139.253,57.352 ; 139.253,57.084 139.761,57.084 ; 139.253,57.352 139.761,57.352 ; 139.253,59.825 139.761,59.825 ; 139.253,59.825 EC16.2@139.253,60.132 ; EC16.2@139.253,60.132 139.761,60.132 ; EC16.2@139.253,60.132 EC16.2@139.253,60.64 ; EC16.2@139.253,60.64 139.72,60.64 ; EC16.2@139.253,60.64 EC16.2@139.253,61.148 ; EC16.2@139.253,61.148 EC16.2@139.253,61.562 ; EC16.2@139.253,61.148 139.74,61.148 ; EC16.2@139.253,61.562 139.761,61.562 ; 139.253,92.703 139.761,92.703 ; 139.253,92.703 139.253,93.152 ; 139.253,93.152 139.761,93.152 ; 139.253,93.152 139.253,93.66 ; 139.253,93.66 139.761,93.66 ; 139.253,93.66 139.253,94.168 ; 139.253,94.168 pad.@139.761,94.168 ; 139.253,94.168 139.253,94.676 ; 139.253,94.676 139.634,94.676 ; 139.253,94.676 139.253,95.056 pad.@139.253,95.057 ; pad.@139.253,95.057 139.254,95.056 139.634,94.676 ; 139.444,65.339 cw(c138.804,64.704) 139.549,65.212 ; 139.444,66.609 cw(c138.804,65.974) 139.669,66.228 ; 139.444,66.609 ccw(c138.804,67.244) 139.549,66.736 ; 139.444,67.879 cw(c138.804,67.244) 139.549,67.752 ; 139.444,67.879 ccw(c138.804,68.514) 139.669,68.26 ; 139.549,64.196 ccw(c138.804,64.704) 139.706,64.704 ; 139.549,64.196 139.761,64.196 ; 139.549,65.212 cw(c138.804,64.704) 139.706,64.704 ; 139.549,65.212 139.761,65.212 ; 139.549,66.736 ccw(c138.804,67.244) 139.706,67.244 ; 139.549,66.736 139.761,66.736 ; 139.549,67.752 cw(c138.804,67.244) 139.706,67.244 ; 139.549,67.752 139.761,67.752 ; 139.634,94.676 139.761,94.549 ; 139.669,66.228 139.761,66.228 ; 139.669,68.26 ccw(c138.804,68.514) 139.706,68.514 ccw(c138.804,68.514) 139.669,68.768 ; 139.669,68.26 139.761,68.26 ; 139.669,68.768 139.761,68.768 ; 139.706,64.704 139.761,64.704 ; 139.706,67.244 139.761,67.244 ; 139.72,60.64 139.72,60.617 ccw(c141.072,60.617) 139.761,60.29 ccw(c141.072,60.617) 139.761,60.288 ; 139.72,60.64 139.72,60.917 cw(c141.072,60.917) 139.74,61.148 ; 139.74,61.148 cw(c141.072,60.917) 139.761,61.246 ; 139.761,53.306 140.16,53.306 ; 139.761,53.306 139.761,53.528 ; 139.761,53.528 R56.2@139.761,54.036 ; 139.761,53.528 140.16,53.528 ; R56.2@139.761,54.036 140.16,54.036 ; R56.2@139.761,54.036 R56.2@139.761,54.544 ; R56.2@139.761,54.544 140.16,54.544 ; R56.2@139.761,54.544 R56.2@139.761,55.052 ; R56.2@139.761,55.052 139.761,55.56 ; R56.2@139.761,55.052 140.16,55.052 ; 139.761,55.56 139.761,56.068 ; 139.761,55.56 140.16,55.56 ; 139.761,56.068 139.761,56.576 ; 139.761,56.068 140.175,56.068 ; 139.761,56.576 139.761,57.084 ; 139.761,56.576 140.175,56.576 ; 139.761,57.084 140.044,57.084 ; 139.761,57.084 139.761,57.352 ; 139.761,57.352 139.776,57.352 140.044,57.084 ; 139.761,59.825 139.761,60.132 ; 139.761,59.825 139.976,59.825 ; 139.761,60.132 139.81,60.132 ; 139.761,60.132 139.761,60.288 ; 139.761,60.288 ccw(c141.072,60.617) 139.81,60.132 ; 139.761,61.246 cw(c141.072,60.917) 139.884,61.562 ; 139.761,61.246 139.761,61.562 ; 139.761,61.562 139.884,61.562 ; 139.761,63.782 139.761,64.196 ; 139.761,63.782 139.936,63.782 ; 139.761,64.196 139.761,64.704 ; 139.761,64.196 140.269,64.196 ; 139.761,64.704 139.761,65.212 ; 139.761,64.704 140.269,64.704 ; 139.761,65.212 139.761,65.72 ; 139.761,65.212 140.269,65.212 ; 139.761,65.72 139.761,66.228 ; 139.761,65.72 140.269,65.72 ; 139.761,66.228 139.761,66.736 ; 139.761,66.228 140.269,66.228 ; 139.761,66.736 139.761,67.244 ; 139.761,66.736 pad.@140.269,66.736 ; 139.761,67.244 139.761,67.752 ; 139.761,67.244 140.269,67.244 ; 139.761,67.752 139.761,68.26 ; 139.761,67.752 140.269,67.752 ; 139.761,68.26 139.761,68.768 ; 139.761,68.26 140.269,68.26 ; 139.761,68.768 139.761,68.928 ; 139.761,68.768 140.269,68.768 ; 139.761,68.928 140.269,68.928 ; 139.761,92.703 140.269,92.703 ; 139.761,92.703 139.761,93.152 ; 139.761,93.152 140.269,93.152 ; 139.761,93.152 139.761,93.66 ; 139.761,93.66 pad.@139.761,94.168 ; 139.761,93.66 140.269,93.66 ; pad.@139.761,94.168 139.761,94.549 ; pad.@139.761,94.168 pad.@140.142,94.168 ; 139.761,94.549 pad.@140.142,94.168 ; 139.81,60.132 ccw(c141.072,60.617) 139.976,59.825 ; 139.936,63.782 ccw(c140.715,62.991) 139.93,63.776 cw(c140.715,62.991) 139.936,63.782 ; 139.936,63.782 cw(c140.715,62.991) 140.264,64.005 ; 139.936,63.782 cw(c140.715,62.991) 140.264,64.005 ; pad.@140.142,94.168 pad.@140.269,94.041 ; 140.16,53.306 140.16,53.528 ; 140.16,53.528 140.16,54.036 ; 140.16,54.036 140.16,54.544 ; 140.16,54.544 140.16,55.052 ; 140.16,55.052 140.16,55.56 ; 140.175,56.068 140.175,56.576 ; 140.175,56.576 140.175,56.739 ; 140.175,56.739 cw(c141.412,56.739) 140.191,56.932 ccw(c141.412,56.739) 140.175,56.739 ; 140.264,64.005 cw(c140.715,62.991) 140.269,64.007 ; 140.264,64.005 cw(c140.715,62.991) 140.269,64.007 ; 140.269,64.007 cw(c140.715,62.991) 140.715,64.101 ; 140.269,64.007 cw(c140.715,62.991) 140.715,64.101 ; 140.269,64.007 140.269,64.196 ; 140.269,64.196 140.777,64.196 ; 140.269,64.196 140.269,64.704 ; 140.269,64.704 140.777,64.704 ; 140.269,64.704 140.269,65.212 ; 140.269,65.212 140.777,65.212 ; 140.269,65.212 140.269,65.72 ; 140.269,65.72 140.269,66.228 ; 140.269,65.72 140.777,65.72 ; 140.269,66.228 pad.@140.269,66.736 ; 140.269,66.228 140.777,66.228 ; pad.@140.269,66.736 140.777,66.736 ; pad.@140.269,66.736 140.269,67.244 ; 140.269,67.244 140.777,67.244 ; 140.269,67.244 140.269,67.752 ; 140.269,67.752 140.777,67.752 ; 140.269,67.752 140.269,68.26 ; 140.269,68.26 140.777,68.26 ; 140.269,68.26 140.269,68.768 ; 140.269,68.768 140.777,68.768 ; 140.269,68.768 140.269,68.928 ; 140.269,68.928 140.777,68.928 ; 140.269,92.703 140.269,93.152 ; 140.269,92.703 140.777,92.703 ; 140.269,93.152 pad.@140.777,93.152 ; 140.269,93.152 140.269,93.66 ; 140.269,93.66 140.65,93.66 ; 140.269,93.66 140.269,93.955 pad.@140.269,94.041 ; pad.@140.269,94.041 140.355,93.955 140.65,93.66 ; 140.65,93.66 140.777,93.533 ; 140.715,64.101 140.777,64.101 ; 140.777,64.101 140.777,64.196 ; 140.777,64.101 141.285,64.101 ; 140.777,64.196 140.777,64.704 ; 140.777,64.196 141.285,64.196 ; 140.777,64.704 140.777,65.212 ; 140.777,64.704 141.285,64.704 ; 140.777,65.212 140.777,65.72 ; 140.777,65.212 141.285,65.212 ; 140.777,65.72 140.777,66.228 ; 140.777,65.72 141.285,65.72 ; 140.777,66.228 140.777,66.736 ; 140.777,66.228 141.285,66.228 ; 140.777,66.736 140.777,67.244 ; 140.777,66.736 141.285,66.736 ; 140.777,67.244 140.777,67.752 ; 140.777,67.244 141.285,67.244 ; 140.777,67.752 140.777,68.26 ; 140.777,67.752 141.285,67.752 ; 140.777,68.26 140.777,68.768 ; 140.777,68.26 141.285,68.26 ; 140.777,68.768 140.777,68.928 ; 140.777,68.768 141.285,68.768 ; 140.777,68.928 141.285,68.928 ; 140.777,92.703 pad.@140.777,93.152 ; 140.777,92.703 141.285,92.703 ; pad.@140.777,93.152 141.158,93.152 ; pad.@140.777,93.152 140.777,93.533 ; 140.777,93.533 141.158,93.152 ; 141.158,93.152 141.285,93.025 ; 141.285,64.101 141.793,64.101 ; 141.285,64.101 141.285,64.196 ; 141.285,64.196 141.793,64.196 ; 141.285,64.196 141.285,64.704 ; 141.285,64.704 141.793,64.704 ; 141.285,64.704 141.285,65.212 ; 141.285,65.212 141.793,65.212 ; 141.285,65.212 141.285,65.72 ; 141.285,65.72 141.285,66.228 ; 141.285,65.72 141.793,65.72 ; 141.285,66.228 141.285,66.736 ; 141.285,66.228 141.793,66.228 ; 141.285,66.736 141.793,66.736 ; 141.285,66.736 141.285,67.244 ; 141.285,67.244 141.793,67.244 ; 141.285,67.244 141.285,67.752 ; 141.285,67.752 141.793,67.752 ; 141.285,67.752 141.285,68.26 ; 141.285,68.26 141.285,68.768 ; 141.285,68.26 pad.@141.793,68.26 ; 141.285,68.768 141.793,68.768 ; 141.285,68.768 141.285,68.928 ; 141.285,68.928 141.793,68.928 ; 141.285,92.703 141.607,92.703 141.454,92.856 141.412,92.898 141.285,93.025 ; 141.285,92.703 141.285,93.025 ; 141.335,59.291 ccw(c141.072,60.617) 141.793,59.474 ; 141.335,59.291 141.51,59.116 ; 141.475,73.34 cw(c141.196,74.013) 141.445,73.328 ccw(c141.196,74.013) 141.475,73.34 ; 141.475,73.34 ccw(c141.196,74.013) pad.@141.711,73.498 ; 141.475,73.34 ccw(c141.196,74.013) pad.@141.711,73.498 ; 141.475,73.34 pad.@141.793,73.34 ; 141.51,59.116 141.793,59.116 ; 141.51,59.116 141.634,58.991 141.793,58.991 ; pad.@141.711,73.498 pad.@141.793,73.58 ; 141.793,58.991 142.301,58.991 ; 141.793,58.991 141.793,59.116 ; 141.793,59.116 142.301,59.116 ; 141.793,59.116 141.793,59.474 ; 141.793,59.474 ccw(c141.072,60.617) 141.989,59.624 ; 141.793,64.101 141.793,64.196 ; 141.793,64.101 142.334,64.101 cw(c143.004,64.704) 142.259,64.196 ; 141.793,64.196 141.793,64.704 ; 141.793,64.196 142.259,64.196 ; 141.793,64.704 141.793,65.212 ; 141.793,64.704 142.102,64.704 ; 141.793,65.212 141.793,65.72 ; 141.793,65.212 142.259,65.212 ; 141.793,65.72 141.793,66.228 ; 141.793,65.72 142.139,65.72 ; 141.793,66.228 141.793,66.736 ; 141.793,66.736 141.793,67.244 ; 141.793,66.736 142.259,66.736 ; 141.793,67.244 141.793,67.752 ; 141.793,67.244 142.102,67.244 ; 141.793,67.752 pad.@141.793,68.26 ; 141.793,67.752 142.259,67.752 ; pad.@141.793,68.26 141.793,68.768 ; pad.@141.793,68.26 142.301,68.26 ; 141.793,68.768 141.793,68.928 ; 141.793,68.768 142.301,68.768 ; 141.793,68.928 142.301,68.928 ; pad.@141.793,73.116 pad.@141.793,73.34 ; pad.@141.793,73.116 pad.@142.301,73.116 ; pad.@141.793,73.34 pad.@141.793,73.58 ; pad.@141.793,73.34 pad.@142.301,73.34 ; pad.@141.793,73.58 pad.@142.061,73.848 ; 141.989,59.624 ccw(c141.072,60.617) 142.301,60.055 ; 141.989,59.624 142.301,59.624 ; pad.@142.061,73.848 142.301,74.088 ; pad.@142.061,73.848 pad.@142.301,73.848 ; 142.102,64.704 ccw(c143.004,64.704) 142.259,64.196 ; 142.102,64.704 cw(c143.004,64.704) 142.259,65.212 ; 142.102,67.244 ccw(c143.004,67.244) 142.259,66.736 ; 142.102,67.244 cw(c143.004,67.244) 142.259,67.752 ; 142.139,65.72 ccw(c143.004,65.974) 142.301,65.41 ; 142.259,65.212 cw(c143.004,64.704) 142.301,65.268 ; 142.259,66.736 ccw(c143.004,67.244) 142.301,66.68 ; 142.259,67.752 cw(c143.004,67.244) 142.301,67.808 ; 142.301,58.991 142.809,58.991 ; 142.301,58.991 142.301,59.116 ; 142.301,59.116 142.809,59.116 ; 142.301,59.116 142.301,59.624 ; 142.301,59.624 142.809,59.624 ; 142.301,59.624 142.301,60.055 ; 142.301,60.055 ccw(c141.072,60.617) 142.334,60.132 ; 142.301,61.479 cw(c141.072,60.917) 142.404,61.148 ; 142.301,61.479 142.301,61.656 ; 142.301,61.656 pad.@142.809,61.656 ; 142.301,65.269 142.301,65.409 ; 142.301,66.539 cw(c143.004,65.974) 142.364,66.609 ; 142.301,66.539 142.301,66.679 ; 142.301,66.679 ccw(c143.004,67.244) 142.364,66.609 ; 142.301,67.809 cw(c143.004,67.244) 142.809,68.124 ; 142.301,67.809 142.301,68.26 ; 142.301,68.26 142.301,68.514 142.301,68.768 ; 142.301,68.26 142.809,68.26 ; 142.301,68.768 142.301,68.928 ; 142.301,68.768 142.809,68.768 ; 142.301,68.928 142.809,68.928 ; pad.@142.301,73.116 142.809,73.116 ; pad.@142.301,73.116 pad.@142.301,73.34 ; pad.@142.301,73.34 142.809,73.34 ; pad.@142.301,73.34 pad.@142.301,73.848 ; pad.@142.301,73.848 142.809,73.848 ; pad.@142.301,73.848 142.301,74.088 ; 142.301,74.088 142.569,74.356 ; 142.334,60.132 ccw(c141.072,60.617) 142.424,60.617 142.424,60.64 ; 142.334,60.132 142.809,60.132 ; 142.404,61.148 cw(c141.072,60.917) 142.424,60.917 142.424,60.64 ; 142.404,61.148 142.809,61.148 ; 142.424,60.64 142.809,60.64 ; 142.569,74.356 142.809,74.596 ; 142.569,74.356 142.809,74.356 ; 142.809,58.991 142.809,59.116 ; 142.809,59.116 143.317,59.116 ; 142.809,59.116 142.809,59.624 ; 142.809,59.624 143.317,59.624 ; 142.809,59.624 142.809,60.132 ; 142.809,60.132 143.317,60.132 ; 142.809,60.132 142.809,60.64 ; 142.809,60.64 143.317,60.64 ; 142.809,60.64 142.809,61.148 ; 142.809,61.148 143.317,61.148 ; 142.809,61.148 pad.@142.809,61.656 ; pad.@142.809,61.656 pad.@142.809,61.881 ; pad.@142.809,61.656 143.317,61.656 ; pad.@142.809,61.881 143.317,61.881 ; 142.809,68.124 cw(c143.004,67.244) 143.004,68.146 143.317,68.146 ; 142.809,68.124 142.809,68.26 ; 142.809,68.26 IC1.4@143.317,68.26 ; 142.809,68.26 142.809,68.514 142.809,68.768 ; 142.809,68.768 142.809,68.928 ; 142.809,68.768 IC1.4@143.317,68.768 ; 142.809,68.928 143.317,68.928 ; 142.809,73.116 TP31.1@143.317,73.116 ; 142.809,73.116 142.809,73.34 ; 142.809,73.34 TP31.1@143.317,73.34 ; 142.809,73.34 142.809,73.674 142.809,73.848 ; 142.809,73.848 TP31.1@143.317,73.848 ; 142.809,73.848 142.809,74.356 ; 142.809,74.356 TP31.1@143.317,74.356 ; 142.809,74.356 142.809,74.596 ; 142.809,74.596 143.07,74.857 ; 143.07,74.857 ccw(c142.555,75.372) 143.077,74.864 ; 143.07,74.857 ccw(c142.555,75.372) 143.077,74.864 ; 143.077,74.864 ccw(c142.555,75.372) 143.284,75.372 ; 143.077,74.864 ccw(c142.555,75.372) 143.284,75.372 ; 143.077,74.864 143.317,74.864 ; 143.284,75.372 143.284,75.88 ; 143.284,75.372 143.317,75.372 ; 143.284,75.88 143.284,76.388 ; 143.284,75.88 143.317,75.88 ; 143.284,76.388 143.317,76.388 ; 143.284,76.388 143.284,76.848 143.317,76.882 ; 143.317,59.021 143.317,59.116 ; 143.317,59.021 143.698,59.021 143.698,59.116 ; 143.317,59.116 143.317,59.624 ; 143.317,59.116 143.698,59.116 ; 143.317,59.624 143.317,60.132 ; 143.317,59.624 C86.2@143.698,59.624 ; 143.317,60.132 143.317,60.64 ; 143.317,60.132 C86.2@143.698,60.132 ; 143.317,60.64 143.317,61.148 ; 143.317,60.64 C86.2@143.698,60.64 ; 143.317,61.148 143.317,61.56 143.317,61.656 ; 143.317,61.148 143.698,61.148 ; 143.317,61.656 143.317,61.881 ; 143.317,61.656 143.698,61.656 ; 143.317,61.881 143.698,61.881 143.698,61.656 ; 143.317,68.146 IC1.4@143.317,68.26 ; 143.317,68.146 143.698,68.146 IC1.4@143.698,68.26 ; IC1.4@143.317,68.26 IC1.4@143.698,68.26 ; IC1.4@143.317,68.26 143.317,68.514 IC1.4@143.317,68.768 ; IC1.4@143.317,68.768 143.317,68.928 ; IC1.4@143.317,68.768 IC1.4@143.698,68.768 ; 143.317,68.928 143.698,68.928 IC1.4@143.698,68.768 ; TP31.1@143.317,73.116 TP31.1@143.317,73.34 ; TP31.1@143.317,73.116 TP31.1@143.825,73.116 ; TP31.1@143.317,73.34 TP31.1@143.825,73.34 ; TP31.1@143.317,73.34 TP31.1@143.317,73.848 ; TP31.1@143.317,73.848 TP31.1@143.317,74.356 ; TP31.1@143.317,73.848 TP31.1@143.825,73.848 ; TP31.1@143.317,74.356 143.317,74.864 ; TP31.1@143.317,74.356 TP31.1@143.825,74.356 ; 143.317,74.864 143.825,74.864 ; 143.317,74.864 143.317,75.372 ; 143.317,75.372 143.825,75.372 ; 143.317,75.372 143.317,75.88 ; 143.317,75.88 143.825,75.88 ; 143.317,75.88 143.317,76.388 ; 143.317,76.388 143.825,76.388 ; 143.317,76.388 143.317,76.882 ; 143.317,76.882 143.331,76.896 ; 143.331,76.896 143.825,77.39 ; 143.331,76.896 143.825,76.896 ; 143.698,59.116 C86.2@143.698,59.624 ; C86.2@143.698,59.624 C86.2@143.698,60.132 ; C86.2@143.698,60.132 C86.2@143.698,60.64 ; C86.2@143.698,60.64 143.698,61.148 ; 143.698,61.148 143.698,61.56 143.698,61.656 ; IC1.4@143.698,68.26 143.698,68.514 IC1.4@143.698,68.768 ; TP31.1@143.825,73.116 TP31.1@143.825,73.34 ; TP31.1@143.825,73.116 144.333,73.116 ; TP31.1@143.825,73.34 TP31.1@144.333,73.34 ; TP31.1@143.825,73.34 TP31.1@143.825,73.848 ; TP31.1@143.825,73.848 TP31.1@144.333,73.848 ; TP31.1@143.825,73.848 TP31.1@143.825,74.356 ; TP31.1@143.825,74.356 144.333,74.356 ; TP31.1@143.825,74.356 143.825,74.864 ; 143.825,74.864 144.333,74.864 ; 143.825,74.864 143.825,75.372 ; 143.825,75.372 144.333,75.372 ; 143.825,75.372 143.825,75.88 ; 143.825,75.88 144.333,75.88 ; 143.825,75.88 143.825,76.388 ; 143.825,76.388 144.333,76.388 ; 143.825,76.388 143.825,76.896 ; 143.825,76.896 144.333,76.896 ; 143.825,76.896 143.825,77.39 ; 143.825,77.39 143.839,77.404 ; 143.839,77.404 144.333,77.404 ; 143.839,77.404 144.137,77.702 ; 144.137,77.702 ccw(c143.622,78.217) 144.284,77.912 ; 144.137,77.702 ccw(c143.622,78.217) 144.284,77.912 ; 144.284,77.912 ccw(c143.622,78.217) 144.333,78.058 ; 144.284,77.912 ccw(c143.622,78.217) 144.333,78.058 ; 144.284,77.912 144.333,77.912 ; 144.333,73.116 TP31.1@144.333,73.34 ; 144.333,73.116 144.841,73.116 ; TP31.1@144.333,73.34 144.841,73.34 ; TP31.1@144.333,73.34 TP31.1@144.333,73.848 ; TP31.1@144.333,73.848 pad.@144.841,73.848 ; TP31.1@144.333,73.848 144.333,74.356 ; 144.333,74.356 pad.@144.841,74.356 ; 144.333,74.356 144.333,74.864 ; 144.333,74.864 144.841,74.864 ; 144.333,74.864 144.333,75.372 ; 144.333,75.372 pad.@144.841,75.372 ; 144.333,75.372 144.333,75.88 ; 144.333,75.88 144.841,75.88 ; 144.333,75.88 144.333,76.388 ; 144.333,76.388 144.841,76.388 ; 144.333,76.388 144.333,76.896 ; 144.333,76.896 144.841,76.896 ; 144.333,76.896 144.333,77.404 ; 144.333,77.404 144.841,77.404 ; 144.333,77.404 144.333,77.912 ; 144.333,77.912 144.841,77.912 ; 144.333,77.912 144.333,78.058 ; 144.333,78.058 ccw(c143.622,78.217) 144.351,78.217 ; 144.333,78.058 ccw(c143.622,78.217) 144.351,78.217 ; 144.351,78.217 144.351,78.42 ; 144.351,78.42 144.351,78.928 ; 144.351,78.42 144.841,78.42 ; 144.351,78.928 144.841,78.928 ; 144.351,78.928 144.351,79.436 ; 144.351,79.436 144.841,79.436 ; 144.351,79.436 144.351,79.944 ; 144.351,79.944 144.841,79.944 ; 144.351,79.944 144.351,80.452 ; 144.351,80.452 144.841,80.452 ; 144.351,80.452 144.351,80.96 ; 144.351,80.96 144.841,80.96 ; 144.351,80.96 144.351,81.468 ; 144.351,81.468 144.841,81.468 ; 144.351,81.468 144.351,81.976 ; 144.351,81.976 144.841,81.976 ; 144.351,81.976 144.351,82.484 ; 144.351,82.484 144.841,82.484 ; 144.351,82.484 144.351,82.992 ; 144.351,82.992 144.841,82.992 ; 144.351,82.992 144.351,83.5 ; 144.351,83.5 144.841,83.5 ; 144.351,83.5 144.351,84.008 ; 144.351,84.008 144.841,84.008 ; 144.351,84.008 144.351,84.338 ; 144.351,84.338 ccw(c144.396,85.32) 144.841,84.444 ; 144.841,73.116 144.841,73.34 ; 144.841,73.116 144.878,73.116 145.102,73.34 ; 144.841,73.34 145.102,73.34 ; 144.841,73.34 pad.@144.841,73.848 ; pad.@144.841,73.848 pad.@144.841,74.356 ; pad.@144.841,73.848 pad.@145.349,73.848 ; pad.@144.841,74.356 144.841,74.864 ; pad.@144.841,74.356 pad.@145.349,74.356 ; 144.841,74.864 pad.@145.349,74.864 ; 144.841,74.864 pad.@144.841,75.372 ; pad.@144.841,75.372 pad.@145.349,75.372 ; pad.@144.841,75.372 144.841,75.88 ; 144.841,75.88 145.349,75.88 ; 144.841,75.88 144.841,76.388 ; 144.841,76.388 145.349,76.388 ; 144.841,76.388 144.841,76.896 ; 144.841,76.896 145.349,76.896 ; 144.841,76.896 144.841,77.404 ; 144.841,77.404 145.349,77.404 ; 144.841,77.404 144.841,77.912 ; 144.841,77.912 pad.@145.349,77.912 ; 144.841,77.912 144.841,78.42 ; 144.841,78.42 145.349,78.42 ; 144.841,78.42 144.841,78.928 ; 144.841,78.928 144.841,79.436 ; 144.841,78.928 145.349,78.928 ; 144.841,79.436 144.841,79.944 ; 144.841,79.436 145.349,79.436 ; 144.841,79.944 144.841,80.452 ; 144.841,79.944 pad.@145.349,79.944 ; 144.841,80.452 144.841,80.96 ; 144.841,80.452 145.349,80.452 ; 144.841,80.96 144.841,81.468 ; 144.841,80.96 145.349,80.96 ; 144.841,81.468 144.841,81.976 ; 144.841,81.468 145.349,81.468 ; 144.841,81.976 144.841,82.484 ; 144.841,81.976 pad.@145.349,81.976 ; 144.841,82.484 144.841,82.992 ; 144.841,82.484 145.349,82.484 ; 144.841,82.992 144.841,83.5 ; 144.841,82.992 145.349,82.992 ; 144.841,83.5 144.841,84.008 ; 144.841,83.5 145.349,83.5 ; 144.841,84.008 145.349,84.008 ; 144.841,84.008 144.841,84.444 ; 144.841,84.444 ccw(c144.396,85.32) 144.961,84.516 ; 144.961,84.516 145.349,84.516 ; 145.102,73.34 145.229,73.467 pad.@145.349,73.587 ; pad.@145.349,73.587 pad.@145.349,73.848 ; pad.@145.349,73.587 145.73,73.968 145.73,74.167 145.73,74.356 ; pad.@145.349,73.848 145.349,74.167 pad.@145.349,74.356 ; pad.@145.349,74.356 pad.@145.349,74.864 ; pad.@145.349,74.356 145.73,74.356 ; pad.@145.349,74.864 145.699,74.864 pad.@145.73,74.864 ; pad.@145.349,74.864 pad.@145.349,75.372 ; pad.@145.349,75.372 145.349,75.88 ; pad.@145.349,75.372 pad.@145.73,75.372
